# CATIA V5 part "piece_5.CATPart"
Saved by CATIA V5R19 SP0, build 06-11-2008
Part number: piece_5
Bounding box of the stored display mesh (mm): x -15 to 45, y 0 to 14, z -5 to 20
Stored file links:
  H:\EU_thinkMotion\IAO_2010\iao\IAO_MMS_Groupe3\PB\jpeguet\jpeguet_IAO\jpeguet_IAO\piece_5.CATPart
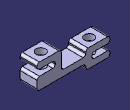
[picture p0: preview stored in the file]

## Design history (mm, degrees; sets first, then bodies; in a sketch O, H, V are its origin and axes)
Body1 (main body)
  Sketch1 on xy-plane, origin (0, 0, 0), H (1, 0, 0), V (0, 1, 0)
    line L1 (0, 0) -> (45, 0)
    line L2 (45, 0) -> (45, 14)
    line L3 (45, 14) -> (0, 14)
    line L4 (0, 14) -> (0, 0)
    length L2 = 14
    length L3 = 45
    horizontal: L1 H, L3 H
    vertical: L2 V, L4 V
  Pad1: profile Sketch1, direction (0, 0, 1), length 5
  Sketch2 on end face of Pad1, origin (0, 0, 5), H (1, 0, 0), V (0, 1, 0)
    line L1 (25, 14) -> (45, 14)
    line L2 (45, 14) -> (45, 0)
    line L3 (45, 0) -> (25, 0)
    line L4 (25, 0) -> (25, 14)
    reference projected line E1 (55, 14) -> (0, 14) from edge [face of Pad1 from Sketch1.L3 | end face of Pad1]
    reference projected line E2 (0, 0) -> (55, 0) from edge [face of Pad1 from Sketch1.L1 | end face of Pad1]
    reference projected line E3 (45, 0) -> (45, 14) from edge [face of Pad1 from Sketch1.L2 | end face of Pad1]
    line L5 (5, 0) -> (-15, 0)
    line L6 (-15, 0) -> (-15, 14)
    line L7 (-15, 14) -> (5, 14)
    line L8 (5, 14) -> (5, 0)
    reference projected line E4 (55, 14) -> (0, 14) from edge [face of Pad1 from Sketch1.L3 | end face of Pad1]
    reference projected line E5 (0, 0) -> (55, 0) from edge [face of Pad1 from Sketch1.L1 | end face of Pad1]
    reference projected line E6 (0, 14) -> (0, 0) from edge [face of Pad1 from Sketch1.L4 | end face of Pad1]
    reference projected line E7 (0, 14) -> (0, 0) from edge [face of Pad1 from Sketch1.L4 | end face of Pad1]
    distance L4 L2 = 20
    distance L8 E6 = 5
    distance L6 E7 = 15
    horizontal: L1 H, L3 H, L5 H, L7 H
    vertical: L2 V, L4 V, L6 V, L8 V
    coincidence: L1 E1, L3 E2, L2 E3, L7 E4, L5 E5
  Pad2: profile Sketch2, direction (0, 0, 1), length 5
  Sketch3 on start face of Pad1, origin (0, 0, 0), H (1, 0, 0), V (0, -1, 0)
    line L1 (5, 0) -> (-15, 0)
    line L2 (-15, 0) -> (-15, -14)
    line L3 (-15, -14) -> (5, -14)
    line L4 (5, -14) -> (5, 0)
    reference projected line E1 (0, -14) -> (0, 0) from edge [start face of Pad1 | face of Pad1 from Sketch1.L4]
    reference projected line E2 (55, -14) -> (0, -14) from edge [start face of Pad1 | face of Pad2]
    reference projected line E3 (0, 0) -> (55, 0) from edge [start face of Pad1 | face of Pad2]
    reference projected line E4 (-15, -14) -> (-15, 0) from edge [start face of Pad2 | face of Pad2 from Sketch2.L6]
    distance L4 E1 = 5
    horizontal: L1 H, L3 H
    vertical: L2 V, L4 V
    coincidence: L3 E2, L1 E3, L2 E4
  Pad3: profile Sketch3, direction (0, 0, -1), length 5
  Sketch4 on end face of Pad2, origin (0, 0, 10), H (1, 0, 0), V (0, 1, 0)
    line L1 (25, 14) -> (30, 14)
    line L2 (30, 14) -> (30, 0)
    line L3 (30, 0) -> (25, 0)
    line L4 (25, 0) -> (25, 14)
    reference projected line E1 (5, 14) -> (-15, 14) from edge [face of Pad3 | end face of Pad2]
    reference projected line E3 (-15, 0) -> (5, 0) from edge [face of Pad3 | end face of Pad2]
    reference projected line E5 (25, 14) -> (25, 0) from edge [face of Pad2 from Sketch2.L4 | end face of Pad2]
    length L3 = 5
    horizontal: L1 H, L3 H
    vertical: L2 V, L4 V
    coincidence: L1 E1, L3 E3, L4 E5
  Pad4: profile Sketch4, direction (0, 0, 1), length 10
  Sketch5 on face of Pad4 from Sketch4.L2, origin (30, 0, 0), H (0, 1, 0), V (0, 0, 1)
    line L1 (0, 20) -> (14, 20)
    line L2 (14, 20) -> (14, 15)
    line L3 (14, 15) -> (0, 15)
    line L4 (0, 15) -> (0, 20)
    reference projected line E1 (0, 10) -> (0, 20) from edge [face of Pad4 from Sketch4.L2 | face of Pad4]
    reference projected line E2 (14, 10) -> (14, 20) from edge [face of Pad4 | face of Pad4 from Sketch4.L2]
    reference projected line E3 (0, 20) -> (14, 20) from edge [face of Pad4 from Sketch4.L2 | end face of Pad4]
    length L2 = 5
    horizontal: L1 H, L3 H
    vertical: L2 V, L4 V
    coincidence: L4 E1, L2 E2, L1 E3
  Pad5: profile Sketch5, direction (1, 0, 0), length 15
  Fillet1: radius 2, on edge [face of Pad2 from Sketch2.L6 | end face of Pad2]; edge [start face of Pad2 | face of Pad2 from Sketch2.L6]; edge [start face of Pad3 | face of Pad3 from Sketch3.L2]; edge [face of Pad3 from Sketch3.L2 | end face of Pad3]; edge [start face of Pad3 | face of Pad1 from Sketch1.L4]; edge [face of Pad2 from Sketch2.L8 | end face of Pad2]; edge [end face of Pad1 | face of Pad4]; edge [face of Pad4 | face of Pad5]; edge [face of Pad5 | end face of Pad5]; edge [face of Pad2 | end face of Pad2]; edge [end face of Pad1 | face of Pad2 from Sketch2.L8]; edge [start face of Pad1 | face of Pad2]; edge [face of Pad5 from Sketch5.L3 | end face of Pad5]; edge [end face of Pad2 | face of Pad4 from Sketch4.L2]; edge [face of Pad4 from Sketch4.L2 | face of Pad5 from Sketch5.L3]; edge [face of Pad3 from Sketch3.L4 | end face of Pad3]; edge [start face of Pad1 | face of Pad3 from Sketch3.L4]; edge [face of Pad1 from Sketch1.L4 | start face of Pad2]
  Sketch6 on end face of Pad2, origin (-5.6756, 7.5912, 10), H (1, 0, 0), V (0, 1, 0)
    point P1 (0.6756, -0.5912)
    reference projected line E1 (35.6756, 6.4088) -> (50.6756, 6.4088) from edge [face of Pad5 | end face of Pad2]
    reference projected line E3 (8.6756, -7.5912) -> (8.6756, 6.4088) from edge [face of Fillet1 | end face of Pad2]
    distance P1 E1 = 7
    distance P1 E3 = 8
  Hole1: placed by Sketch6, at (-5, 7, 10) direction (0, 0, -1), diameter 8, through (limit type 3)
  Sketch7 on face of Pad5, origin (45.1263, 6.8895, 20), H (1, 0, 0), V (0, 1, 0)
    point P1 (-10.1263, 0.1105)
    reference projected line E1 (-2.1263, 7.1105) -> (-2.1263, -6.8895) from edge [face of Pad5 | face of Fillet1]
    reference projected line E2 (-5.1263, 7.1105) -> (-10.1263, 7.1105) from edge [face of Pad5 | face of Pad5]
    distance P1 E1 = 8
    distance P1 E2 = 7
  Hole2: placed by Sketch7, at (35, 7, 20) direction (0, 0, -1), diameter 8, through (limit type 3)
